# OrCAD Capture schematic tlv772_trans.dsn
size A; title: TLV772 300mA, Small-Size, High-PSRR, Adjustable, Low-Dropout Regulator; rev: 1.0
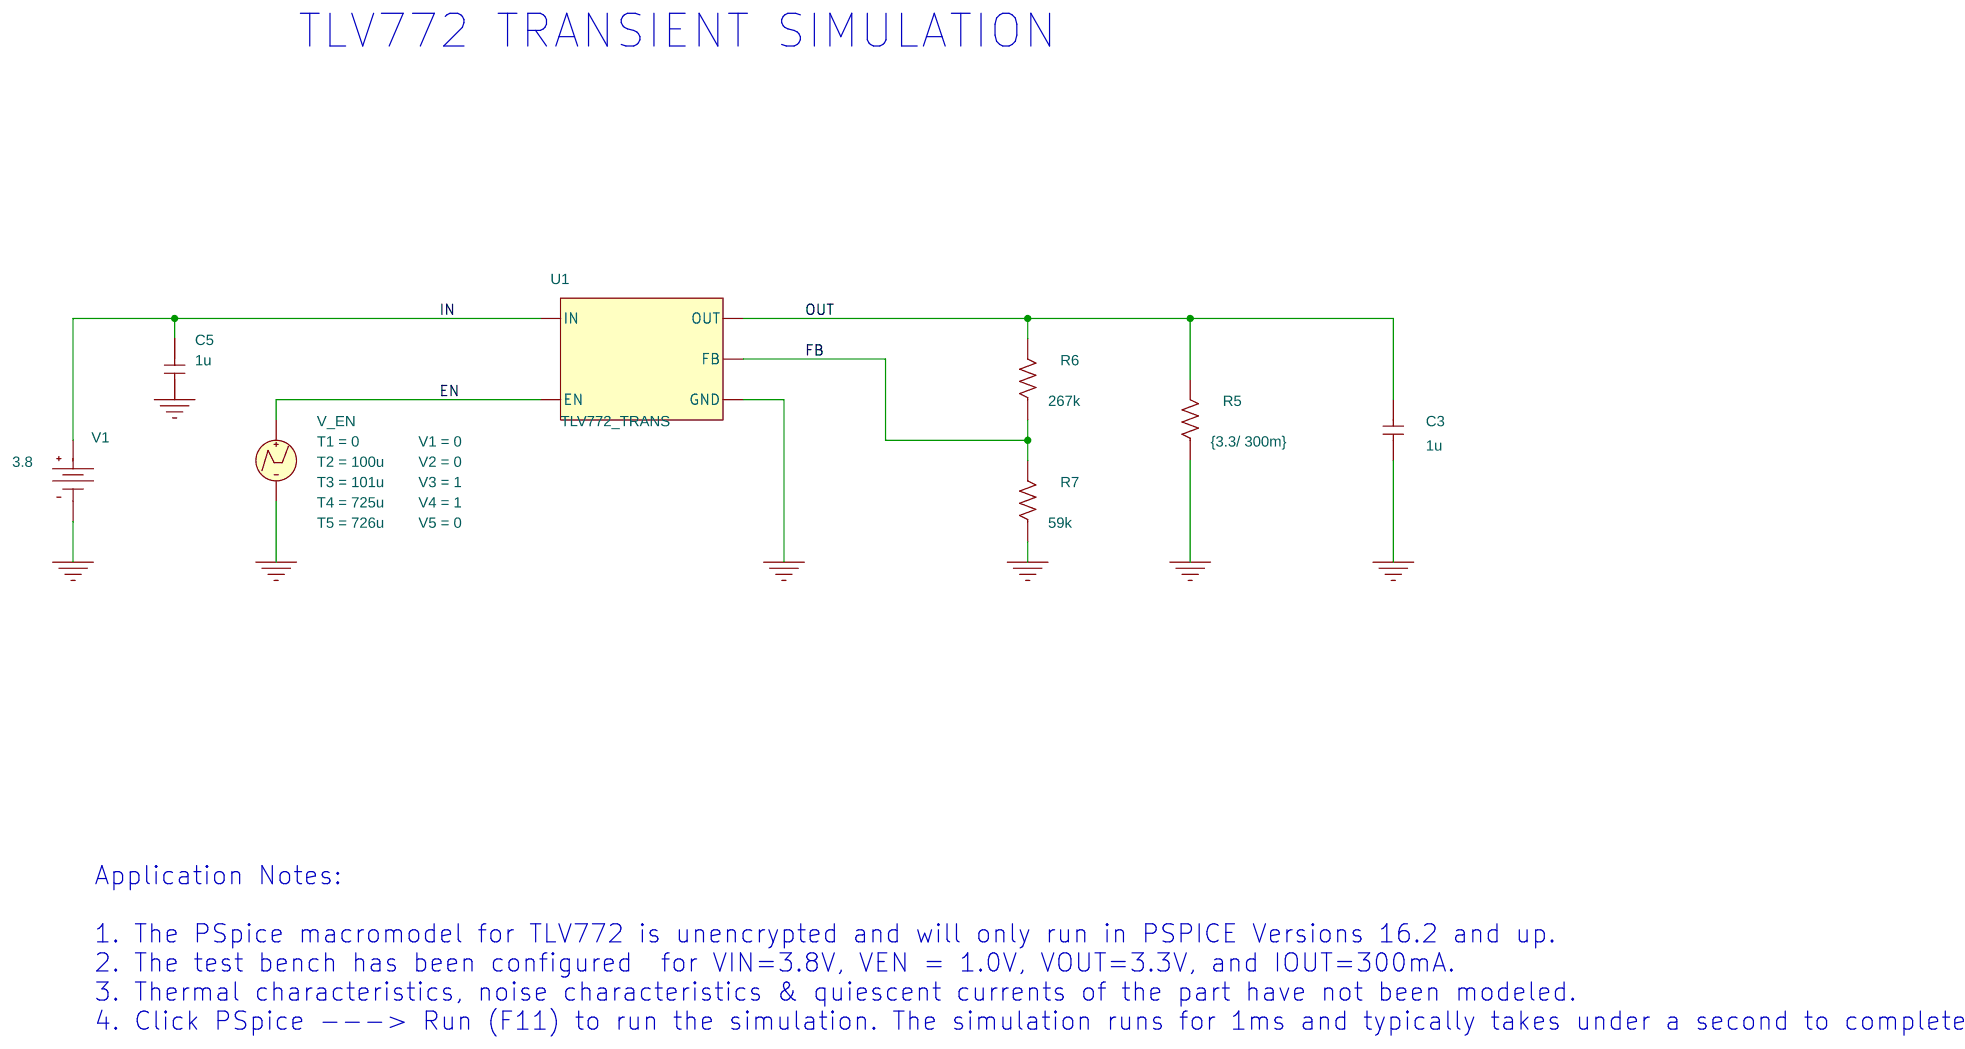
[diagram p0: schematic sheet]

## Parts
C3  1u  [RAD/CK05]
C5  1u  [RAD/CK05]
R5  {3.3/ 300m}  [AX/RC05]
R6  267k  [AX/RC05]
R7  59k  [AX/RC05]
U1  TLV772_TRANS
V1  VDC
V_EN  VPWL

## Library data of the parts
C3 C5 = C
R5-R7 = R
U1 = TLV772_TRANS
V1 = VDC: DC: 3.8
V_EN = VPWL: T1: 0; T2: 100u; T3: 101u; T4: 725u; T5: 726u; V1: 0; V2: 0; V3: 1; V4: 1; V5: 0

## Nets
0: C3.1 C5.1 R5.1 R7.1 U1.GND V1.1(-) V_EN.2(-)
EN: U1.EN V_EN.1(+)
FB: R6.1 R7.2 U1.FB
IN: C5.2 U1.IN V1.0(+)
OUT: C3.2 R5.2 R6.2 U1.OUT

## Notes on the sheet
- TLV772 TRANSIENT SIMULATION
- Application Notes:
  1. The PSpice macromodel for TLV772 is unencrypted and will only run in PSPICE Versions 16.2 and up.
  2. The test bench has been configured  for VIN=3.8V, VEN = 1.0V, VOUT=3.3V, and IOUT=300mA.
  3. Thermal characteristics, noise characteristics & quiescent currents of the part have not been modeled.
  4. Click PSpice ---> Run (F11) to run the simulation. The simulation runs for 1ms and typically takes under a second to complete.
